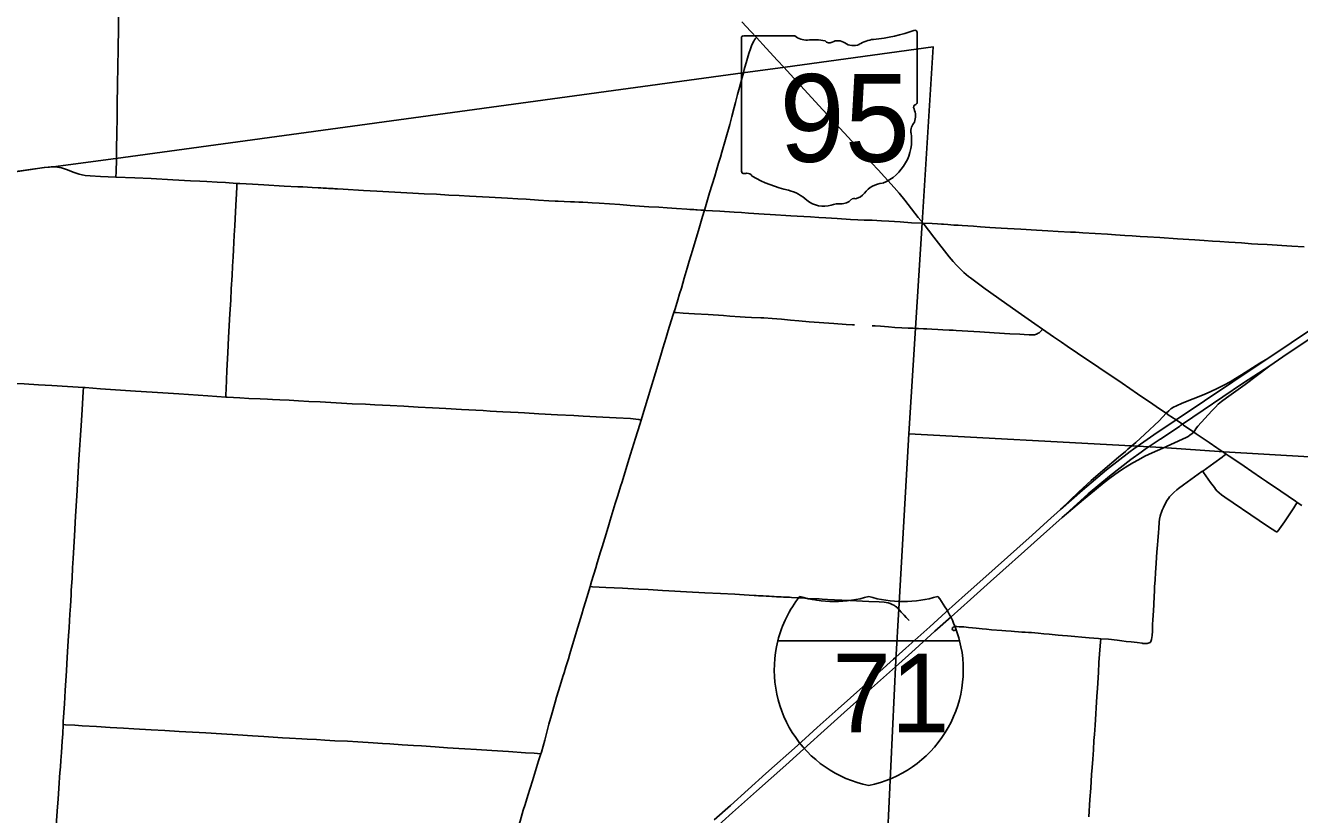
# Model space of a CAD drawing. Extents: x 1815539 to 1947826, y 273303 to 993194.
# Drawn here: x 1889640 to 1909861, y 903282 to 915807 of the extents above; entities that cross this region are included whole.
import ezdxf

# ---------------------------------------------------------------- set-up
doc = ezdxf.new("R2010")
doc.units = 0
for name, color, linetype in [('GM_X_County_Road', 7, 'Continuous'), ('GM_X_Interchange_Ramps', 7, 'Continuous'), ('GM_X_Interstate_Route', 7, 'Continuous'), ('GM_X_Interstate_Shield', 7, 'Continuous'), ('GM_X_State_Route', 7, 'Continuous'), ('GM_X_Township', 7, 'Continuous'), ('GM_X_Township_Road', 7, 'Continuous'), ('SC_Shading3', 7, 'Continuous')]:
    doc.layers.add(name, color=color, linetype=linetype)

msp = doc.modelspace()

# ---------------------------------------------------------------- linework, layer by layer
at = {"layer": 'GM_X_County_Road'}
for points in [[(1901034, 915058), (1901047, 915109), (1901087, 915251), (1901119, 915361), (1901146, 915439), (1901163, 915485), (1901184, 915530), (1901200, 915558), (1901213, 915580), (1901223, 915594), (1901241, 915616)], [(1900416, 912874), (1900432, 912930), (1900499, 913150), (1900581, 913417), (1900609, 913511), (1900642, 913621), (1900670, 913715), (1900692, 913794), (1900751, 913999), (1900817, 914236), (1900852, 914363), (1900889, 914506), (1900909, 914585), (1900943, 914712), (1900972, 914823), (1901013, 914982), (1901034, 915058)], [(1899931, 911252), (1899950, 911310), (1899994, 911451), (1900023, 911545), (1900051, 911640), (1900097, 911797), (1900144, 911955), (1900176, 912065), (1900227, 912238), (1900269, 912379), (1900321, 912552), (1900386, 912773), (1900416, 912874)], [(1903887, 912667), (1904032, 912662), (1904114, 912658), (1904180, 912653), (1904212, 912651), (1904280, 912647), (1904372, 912640), (1904440, 912636), (1904445, 912636)], [(1904445, 912636), (1904506, 912632), (1904686, 912620), (1904800, 912612), (1904948, 912603), (1905128, 912592), (1905226, 912587), (1905439, 912573), (1905684, 912559), (1905864, 912548), (1906028, 912539), (1906224, 912528), (1906306, 912524), (1906421, 912516), (1906617, 912503), (1906813, 912493), (1906942, 912486), (1907089, 912475), (1907204, 912467), (1907334, 912460), (1907449, 912453), (1907645, 912440), (1907923, 912420), (1908103, 912409), (1908202, 912403), (1908349, 912393), (1908480, 912385), (1908594, 912377), (1908741, 912367), (1908938, 912355), (1909101, 912343), (1909199, 912338), (1909347, 912329), (1909740, 912304), (1909936, 912291)], [(1899410, 909541), (1899437, 909631), (1899637, 910291), (1899723, 910574), (1899756, 910684), (1899809, 910856), (1899843, 910966), (1899915, 911201), (1899931, 911252)], [(1887573, 910239), (1887606, 910237), (1887655, 910234), (1887786, 910225), (1887982, 910215), (1888179, 910203), (1888392, 910190), (1888850, 910163), (1889128, 910146), (1889390, 910131), (1889620, 910119), (1889849, 910105), (1890061, 910092), (1890307, 910076), (1890560, 910061)], [(1890238, 904709), (1890241, 904759), (1890260, 905038), (1890272, 905250), (1890290, 905561), (1890297, 905676), (1890309, 905872), (1890323, 906118), (1890332, 906249), (1890346, 906461), (1890354, 906592), (1890364, 906772), (1890368, 906838), (1890379, 907034), (1890389, 907199), (1890398, 907345), (1890418, 907705), (1890435, 908016), (1890455, 908343), (1890469, 908622), (1890488, 908916), (1890523, 909456), (1890533, 909620), (1890543, 909800), (1890556, 909996), (1890560, 910061)], [(1890560, 910061), (1890585, 910059), (1890831, 910042), (1891387, 910005), (1891649, 909988), (1892074, 909958), (1892532, 909928), (1892818, 909909)], [(1892818, 909909), (1892843, 909907), (1893040, 909896), (1893187, 909888), (1893367, 909879), (1893482, 909874), (1893563, 909871), (1893678, 909865), (1893825, 909857), (1893973, 909848), (1894136, 909840), (1894316, 909831), (1894824, 909804), (1895037, 909794), (1895184, 909787), (1895430, 909774), (1895643, 909764), (1895872, 909750), (1896101, 909737), (1896314, 909726), (1896560, 909712), (1896904, 909694), (1897018, 909687), (1897215, 909676), (1897460, 909664), (1897558, 909659), (1897788, 909644), (1898082, 909628), (1898344, 909614), (1898492, 909606), (1898803, 909589), (1899016, 909578), (1899245, 909566), (1899326, 909558), (1899375, 909552), (1899410, 909541)], [(1898602, 906902), (1898625, 906980), (1898691, 907200), (1898715, 907279), (1898769, 907451), (1898792, 907529), (1898835, 907671), (1898888, 907843), (1898921, 907953), (1898954, 908063), (1899002, 908220), (1899041, 908345), (1899085, 908487), (1899109, 908565), (1899201, 908863), (1899244, 909004), (1899322, 909255), (1899390, 909474), (1899410, 909541)], [(1908324, 908735), (1908499, 908861), (1908633, 908955), (1908672, 908985), (1908697, 909005)], [(1907661, 908057), (1907663, 908066), (1907680, 908112), (1907700, 908156), (1907729, 908215), (1907762, 908271), (1907780, 908298), (1907800, 908323), (1907833, 908360), (1907868, 908394), (1907916, 908438), (1907941, 908458), (1908021, 908516), (1908313, 908727), (1908324, 908735)], [(1908324, 908735), (1908339, 908712), (1908375, 908657), (1908450, 908550), (1908509, 908471), (1908529, 908446), (1908551, 908422), (1908587, 908389), (1908624, 908358), (1908677, 908320), (1909220, 907952), (1909369, 907850), (1909483, 907775), (1909492, 907771), (1909501, 907770)], [(1909501, 907770), (1909510, 907774), (1909517, 907781), (1909621, 907930), (1909695, 908039), (1909769, 908148), (1909805, 908204), (1909826, 908236)], [(1907528, 906301), (1907531, 906370), (1907541, 906518), (1907547, 906616), (1907554, 906746), (1907559, 906828), (1907561, 906894), (1907568, 907008), (1907576, 907122), (1907586, 907269), (1907593, 907368), (1907598, 907449), (1907607, 907563), (1907611, 907629), (1907621, 907759), (1907626, 907825), (1907635, 907922), (1907641, 907971), (1907651, 908019), (1907661, 908057)], [(1897819, 904246), (1897828, 904274), (1897881, 904463), (1897949, 904717), (1897988, 904859), (1898045, 905065), (1898068, 905143), (1898126, 905331), (1898170, 905473), (1898188, 905530), (1898219, 905629), (1898259, 905754), (1898282, 905833), (1898370, 906132), (1898408, 906258), (1898470, 906462), (1898498, 906556), (1898555, 906744), (1898597, 906886), (1898602, 906902)], [(1898602, 906902), (1898640, 906899), (1898853, 906887), (1899114, 906873), (1899376, 906859), (1899524, 906852), (1899605, 906848), (1899752, 906839), (1899851, 906833), (1900129, 906818), (1900423, 906802), (1900669, 906790), (1900898, 906778), (1901045, 906768), (1901208, 906759), (1901238, 906757), (1901272, 906755), (1901307, 906753), (1901351, 906751), (1901396, 906749), (1901444, 906746), (1901486, 906744), (1901525, 906742), (1901562, 906740), (1901601, 906738), (1901633, 906737), (1901669, 906735), (1901699, 906733), (1901736, 906732), (1901764, 906730), (1901800, 906728), (1901911, 906723), (1901960, 906720), (1902009, 906716), (1902058, 906713), (1902238, 906705), (1902287, 906703), (1902368, 906698), (1902483, 906692), (1902597, 906687), (1902728, 906681), (1903023, 906666), (1903187, 906658), (1903268, 906652), (1903301, 906647), (1903333, 906641), (1903364, 906631), (1903394, 906618), (1903423, 906603), (1903437, 906595), (1903451, 906586), (1903464, 906577), (1903477, 906567), (1903488, 906555), (1903502, 906540)], [(1903502, 906540), (1903509, 906531), (1903541, 906494), (1903585, 906445), (1903618, 906409), (1903644, 906384), (1903666, 906364)], [(1907041, 906040), (1907112, 906031), (1907188, 906023), (1907282, 906011), (1907362, 906001), (1907376, 905999), (1907425, 905995), (1907441, 905996), (1907458, 906000), (1907474, 906006), (1907488, 906015), (1907500, 906028), (1907508, 906043), (1907513, 906059), (1907519, 906092), (1907522, 906125), (1907525, 906193), (1907528, 906278), (1907528, 906301)], [(1906515, 903244), (1906534, 903523), (1906547, 903702), (1906561, 903915), (1906569, 904029), (1906578, 904160), (1906589, 904307), (1906599, 904455), (1906605, 904553), (1906616, 904700), (1906629, 904880), (1906635, 904978), (1906645, 905157), (1906653, 905288), (1906669, 905534), (1906678, 905697), (1906695, 905959), (1906701, 906017), (1906710, 906072)], [(1906710, 906072), (1906828, 906064), (1906968, 906049), (1907041, 906040)], [(1890074, 902387), (1890082, 902487), (1890099, 902716), (1890116, 902977), (1890125, 903108), (1890143, 903337), (1890157, 903533), (1890176, 903778), (1890182, 903877), (1890186, 903942), (1890195, 904040), (1890202, 904138), (1890210, 904269), (1890222, 904449), (1890231, 904562), (1890238, 904709)], [(1896982, 901567), (1896992, 901599), (1897000, 901626), (1897029, 901721), (1897078, 901878), (1897148, 902097), (1897213, 902300), (1897356, 902754), (1897446, 903035), (1897489, 903176), (1897540, 903349), (1897570, 903443), (1897615, 903583), (1897689, 903818), (1897736, 903976), (1897784, 904133), (1897819, 904246)]]:
    msp.add_lwpolyline(points, dxfattribs=at)
at = {"layer": 'GM_X_Interchange_Ramps'}
for points in [[(1909357, 910519), (1909230, 910449), (1908941, 910262), (1908844, 910201), (1908759, 910152), (1908658, 910097), (1908555, 910045), (1908451, 909997), (1908346, 909952), (1907996, 909810), (1907906, 909771), (1907862, 909749), (1907834, 909732), (1907821, 909722), (1907785, 909688), (1907746, 909651)], [(1908183, 909352), (1908218, 909406), (1908226, 909420), (1908247, 909445), (1908468, 909691), (1908525, 909750), (1908572, 909796), (1908623, 909838), (1908702, 909898), (1908997, 910109), (1909388, 910406)], [(1907746, 909651), (1907632, 909531), (1907406, 909319), (1907261, 909187), (1907138, 909080), (1907098, 909047), (1906988, 908953), (1906737, 908744), (1906554, 908585), (1906357, 908402), (1906069, 908123)], [(1906093, 907999), (1906433, 908281), (1906606, 908428), (1906758, 908553), (1906849, 908623), (1906928, 908681), (1907037, 908755), (1907134, 908817), (1907218, 908867), (1907304, 908915), (1907406, 908968), (1907524, 909025), (1907524, 909026), (1907689, 909100), (1908004, 909239), (1908063, 909267), (1908092, 909284), (1908119, 909303), (1908159, 909332), (1908183, 909352)]]:
    msp.add_lwpolyline(points, dxfattribs=at)
at = {"layer": 'GM_X_Interstate_Route'}
for points in [[(1908334, 909701), (1908957, 910122), (1909388, 910406), (1909597, 910545), (1910155, 910921), (1910468, 911132), (1910616, 911236), (1910775, 911351), (1910919, 911460), (1911087, 911591), (1911278, 911746), (1911323, 911783)], [(1900572, 903196), (1900828, 903427), (1901390, 903931), (1901891, 904380), (1902208, 904664), (1902539, 904960), (1902929, 905310), (1903198, 905551), (1903418, 905748), (1903456, 905781), (1903613, 905924), (1903992, 906263), (1904248, 906493), (1904554, 906767), (1904883, 907063), (1905373, 907500), (1905617, 907719), (1905863, 907937), (1906069, 908123), (1906417, 908433), (1906800, 908754), (1907175, 909043), (1907231, 909086), (1907551, 909310), (1907901, 909545), (1908800, 910150), (1909357, 910519), (1910101, 911019)], [(1907979, 909461), (1908002, 909477), (1908334, 909701)], [(1907655, 909243), (1907962, 909449), (1907979, 909461)], [(1900533, 903016), (1900863, 903312), (1901242, 903651), (1901706, 904067), (1902049, 904373), (1902318, 904614), (1902635, 904899), (1902879, 905118), (1903258, 905457), (1903447, 905627), (1903759, 905906), (1904075, 906192), (1904332, 906421), (1904638, 906695), (1904956, 906979), (1905154, 907156), (1905494, 907460), (1905751, 907689), (1906093, 907999), (1906509, 908375), (1906843, 908654), (1907186, 908918), (1907349, 909034), (1907413, 909080), (1907651, 909240), (1907655, 909243)]]:
    msp.add_lwpolyline(points, dxfattribs=at)
at = {"layer": 'GM_X_Interstate_Shield'}
for p, q in [((1901581, 906040), (1904467, 906040)), ((1904467, 906040), (1901581, 906040)), ((1904467, 906040), (1901581, 906040))]:
    msp.add_line(p, q, dxfattribs=at)
for centre, start, end in [((1903399, 905580), 141.669, 165.8066), ((1902476, 908537), 253.0091, 286.9909), ((1903572, 908537), 253.0091, 286.9909), ((1902649, 905580), 14.1934, 38.331), ((1903399, 905580), 165.8066, 258.463), ((1902649, 905580), 281.537, 14.1934)]:
    msp.add_arc(centre, 1875, start, end, dxfattribs=at)
at = {"layer": 'GM_X_State_Route'}
for points in [[(1901009, 915867), (1901154, 915711), (1901241, 915616), (1901398, 915445), (1901576, 915251), (1901675, 915144), (1901886, 914913), (1902230, 914538), (1902697, 914032), (1902952, 913754), (1903075, 913622), (1903176, 913514), (1903430, 913235), (1903505, 913148), (1903598, 913033), (1903810, 912761), (1903887, 912667), (1904056, 912447), (1904300, 912137), (1904362, 912062), (1904417, 912001), (1904475, 911943), (1904535, 911888), (1904609, 911823), (1904639, 911800)], [(1904639, 911800), (1904661, 911783), (1904873, 911629), (1904926, 911590), (1905125, 911446), (1905448, 911221), (1905662, 911069), (1905782, 910986), (1905958, 910864), (1906082, 910779)], [(1906082, 910779), (1906174, 910715), (1906338, 910606), (1906678, 910377), (1906746, 910331), (1906881, 910238), (1907044, 910128), (1907288, 909962), (1907344, 909924)], [(1907344, 909924), (1907464, 909842), (1907654, 909713), (1907746, 909651), (1907794, 909618)], [(1907794, 909618), (1907830, 909593), (1907833, 909591)], [(1907833, 909591), (1907901, 909545), (1908002, 909477), (1908021, 909464), (1908183, 909352), (1908223, 909325), (1908427, 909187), (1908549, 909105)], [(1908549, 909105), (1908658, 909031), (1908697, 909005), (1908745, 908972)], [(1908745, 908972), (1908821, 908921), (1908984, 908810), (1909105, 908726), (1909257, 908623)], [(1909257, 908623), (1909336, 908570), (1909566, 908413), (1909797, 908256), (1909826, 908236), (1909896, 908189)]]:
    msp.add_lwpolyline(points, dxfattribs=at)
at = {"layer": 'GM_X_Township'}
for points in [[(1930733, 907844), (1927982, 907939), (1924001, 908161), (1918864, 908449), (1913461, 908761), (1908659, 909041), (1907683, 909106), (1907386, 909123), (1907188, 909134), (1903661, 909327), (1903767, 911000), (1903873, 912675), (1904049, 915466), (1901695, 915145), (1901024, 915054), (1891076, 913698), (1890078, 913562), (1889943, 913553), (1889411, 913481)], [(1929313, 880637), (1926519, 880798), (1923978, 880945), (1923826, 880954), (1918127, 881283), (1915079, 881414), (1912418, 881561), (1907482, 881867), (1902065, 882212), (1902276, 885593), (1902366, 887154), (1902378, 887248), (1902624, 890798), (1902935, 895772), (1903241, 901246), (1903453, 905734), (1903500, 906547), (1903661, 909327)]]:
    msp.add_lwpolyline(points, dxfattribs=at)
at = {"layer": 'GM_X_Township_Road'}
for points in [[(1891083, 913706), (1891086, 913892), (1891088, 914056), (1891093, 914384), (1891094, 914436), (1891095, 914497), (1891096, 914543), (1891097, 914601), (1891098, 914682), (1891099, 914738), (1891100, 914809), (1891101, 914872), (1891102, 914923), (1891103, 914982), (1891104, 915047), (1891105, 915121), (1891106, 915168), (1891107, 915220), (1891111, 915366), (1891119, 915841), (1891119, 915923), (1891121, 916152), (1891124, 916277)], [(1891075, 913399), (1891078, 913482), (1891083, 913679), (1891083, 913706)], [(1888253, 913319), (1888267, 913321), (1888379, 913338), (1888476, 913353), (1888573, 913367), (1888670, 913380), (1888784, 913395), (1888914, 913412), (1888946, 913417), (1889027, 913425), (1889092, 913433), (1889125, 913436), (1889206, 913447), (1889303, 913462), (1889514, 913490), (1889693, 913516), (1889936, 913551), (1890001, 913559), (1890021, 913560)], [(1890021, 913560), (1890050, 913562), (1890083, 913563), (1890116, 913561), (1890149, 913558), (1890181, 913552), (1890213, 913545), (1890260, 913531), (1890306, 913514), (1890398, 913477), (1890444, 913461), (1890490, 913447), (1890538, 913435), (1890586, 913428), (1890668, 913421), (1890831, 913410), (1891075, 913399)], [(1891075, 913399), (1891374, 913387), (1891637, 913376), (1891980, 913358), (1892259, 913342), (1892406, 913335), (1892521, 913329), (1892684, 913321), (1892815, 913313), (1892997, 913301)], [(1892818, 909909), (1892820, 909952), (1892824, 910034), (1892830, 910182), (1892836, 910330), (1892850, 910609), (1892865, 910854), (1892886, 911232), (1892897, 911445), (1892907, 911625), (1892919, 911838), (1892927, 911986), (1892935, 912133), (1892942, 912248), (1892954, 912478), (1892963, 912625), (1892968, 912740), (1892981, 912953), (1892989, 913133), (1892995, 913248), (1892996, 913281), (1892997, 913301)], [(1892997, 913301), (1893044, 913298), (1893241, 913286), (1893421, 913277), (1893748, 913258), (1893961, 913247), (1894043, 913244), (1894190, 913236), (1894287, 913231), (1894330, 913228), (1894365, 913226), (1894390, 913225), (1894418, 913223), (1894449, 913221), (1894480, 913219), (1894524, 913217), (1894550, 913215), (1894594, 913212), (1894681, 913207), (1895003, 913188), (1895216, 913176), (1895789, 913147), (1895969, 913136), (1896165, 913127), (1896362, 913116), (1896525, 913108), (1896688, 913099), (1896999, 913082), (1897293, 913065), (1897457, 913055), (1897588, 913048), (1897784, 913035), (1897947, 913026), (1898045, 913020), (1898094, 913018), (1898192, 913013), (1898290, 913009), (1898356, 913006), (1898421, 913004), (1898486, 913000), (1898568, 912995), (1898633, 912991), (1898746, 912985), (1898910, 912974), (1899074, 912963), (1899237, 912951), (1899532, 912931), (1899695, 912921), (1899826, 912913), (1899973, 912902), (1900137, 912893), (1900187, 912888), (1900216, 912886), (1900250, 912884), (1900279, 912881), (1900300, 912880), (1900357, 912877), (1900406, 912874), (1900416, 912874)], [(1900416, 912874), (1900439, 912872), (1900545, 912867), (1900660, 912860), (1900889, 912844), (1901003, 912836), (1901118, 912829), (1901363, 912812), (1901461, 912807), (1901543, 912803), (1901707, 912793), (1901788, 912788), (1901886, 912781), (1902099, 912768), (1902230, 912761), (1902344, 912755), (1902524, 912743), (1902737, 912730), (1902851, 912723), (1902950, 912719), (1903080, 912715), (1903228, 912708), (1903342, 912701), (1903522, 912689), (1903702, 912676), (1903887, 912667)], [(1899931, 911252), (1899966, 911250), (1900081, 911242), (1900261, 911231), (1900475, 911218), (1900720, 911202), (1900819, 911195), (1900982, 911184), (1901064, 911179), (1901162, 911173), (1901310, 911167), (1901359, 911165), (1901490, 911155), (1901637, 911144), (1901784, 911131), (1901915, 911118), (1902079, 911104), (1902471, 911074), (1902668, 911060), (1902766, 911055), (1902799, 911054)], [(1903078, 911039), (1903127, 911038), (1903209, 911033), (1903339, 911022), (1903437, 911013), (1903551, 911006), (1903649, 911003), (1903731, 911001), (1903771, 910999)], [(1903771, 910999), (1903812, 910997), (1903893, 910994), (1903948, 910991), (1904026, 910987), (1904120, 910982), (1904200, 910978), (1904301, 910972), (1904365, 910969), (1904414, 910965), (1904691, 910949), (1904789, 910944), (1905017, 910930), (1905261, 910915), (1905424, 910906), (1905489, 910902), (1905571, 910898), (1905620, 910897), (1905653, 910899), (1905669, 910903), (1905684, 910908), (1905699, 910914), (1905714, 910921), (1905728, 910929), (1905751, 910949), (1905774, 910976), (1905782, 910986)], [(1904407, 906219), (1904395, 906208), (1904379, 906202), (1904364, 906204), (1904352, 906214), (1904348, 906230), (1904352, 906245), (1904363, 906257), (1904378, 906263), (1904393, 906265), (1904408, 906265), (1904420, 906265), (1904422, 906265), (1904461, 906264), (1904489, 906262), (1904531, 906259), (1904572, 906255), (1904606, 906250), (1904671, 906244), (1904731, 906239), (1904826, 906230), (1904891, 906223), (1904973, 906216), (1905137, 906204), (1905202, 906199), (1905284, 906193), (1905338, 906188), (1905400, 906183), (1905456, 906179), (1905507, 906175), (1905559, 906172), (1905606, 906169), (1905715, 906159), (1905803, 906152), (1905885, 906145), (1905933, 906139), (1906031, 906131), (1906097, 906125), (1906178, 906118), (1906522, 906087), (1906669, 906075), (1906710, 906072)], [(1890238, 904709), (1890277, 904708), (1890425, 904698), (1890539, 904691), (1890769, 904678), (1890982, 904664), (1891195, 904654), (1891359, 904643), (1891637, 904627), (1891850, 904614), (1892079, 904600), (1892292, 904589), (1892505, 904577), (1892751, 904563), (1893013, 904546), (1893242, 904530), (1893423, 904520), (1893570, 904512), (1893717, 904502), (1893832, 904496), (1894029, 904485), (1894111, 904480), (1894258, 904473), (1894389, 904464), (1894552, 904454), (1894749, 904444), (1894913, 904434), (1895159, 904420), (1895306, 904410), (1895421, 904402), (1895617, 904387), (1895797, 904377), (1895928, 904370), (1896141, 904357), (1896337, 904342), (1896517, 904330), (1896616, 904324), (1896796, 904314), (1897042, 904297), (1897304, 904281), (1897578, 904262), (1897713, 904254), (1897819, 904246)]]:
    msp.add_lwpolyline(points, dxfattribs=at)
at = {"layer": 'SC_Shading3'}
for p, q in [((1901007, 915607), (1901007, 913494)), ((1901849, 915643), (1901034, 915643)), ((1903791, 914590), (1903791, 915696)), ((1903791, 914590), (1903791, 914590))]:
    msp.add_line(p, q, dxfattribs=at)
for centre, radius, start, end in [((1901038, 915611), 32.3, 98.1301, 188.1301), ((1902044, 915888), 313, 231.6195, 271.1119), ((1902799, 918524), 2953, 275.8445, 288.9065), ((1903760, 915700), 31, 351.8621, 97.738), ((1902147, 914457), 1123, 80.4867, 94.9883), ((1902402, 915622), 90.3, 219.7921, 297.1024), ((1902535, 915378), 188, 54.4667, 119.1411), ((1902777, 915713), 226, 233.8562, 294.8282), ((1903176, 914998), 594, 97.3462, 120.7689), ((1903758, 914586), 33.2, 289.6038, 7.7341), ((1903784, 914509), 48, 107.944, 210.337), ((1903479, 914369), 288, 340.033, 23.6496), ((1903902, 914127), 210, 136.8065, 186.9296), ((1902965, 913987), 739, 292.3089, 8.9858), ((1901039, 913489), 32.5, 171.9584, 258.3066), ((1901044, 913705), 248, 267.339, 280.6039), ((1901095, 913372), 89.5, 29.7484, 93.2717), ((1902225, 915270), 2132, 240.4129, 257.1985), ((1901589, 912544), 667, 47.1842, 75.836), ((1903276, 912900), 404, 94.4031, 142.5768), ((1902311, 913361), 423, 230.7004, 286.2918), ((1902556, 912630), 348, 85.6951, 111.2099), ((1902586, 913203), 226, 268.777, 315.5493), ((1902791, 912998), 63.5, 65.7517, 132.6484), ((1902763, 913289), 239, 282.8732, 323.2771)]:
    msp.add_arc(centre, radius, start, end, dxfattribs=at)

# ---------------------------------------------------------------- texts
at = {"layer": 'GM_X_Interstate_Shield'}
msp.add_text('71', height=1250, dxfattribs=at).set_placement((1902447, 904587))
at = {"layer": 'SC_Shading3'}
msp.add_text('95', height=1392.2, dxfattribs=at).set_placement((1901607, 913643))

doc.saveas('drawing.dxf')
